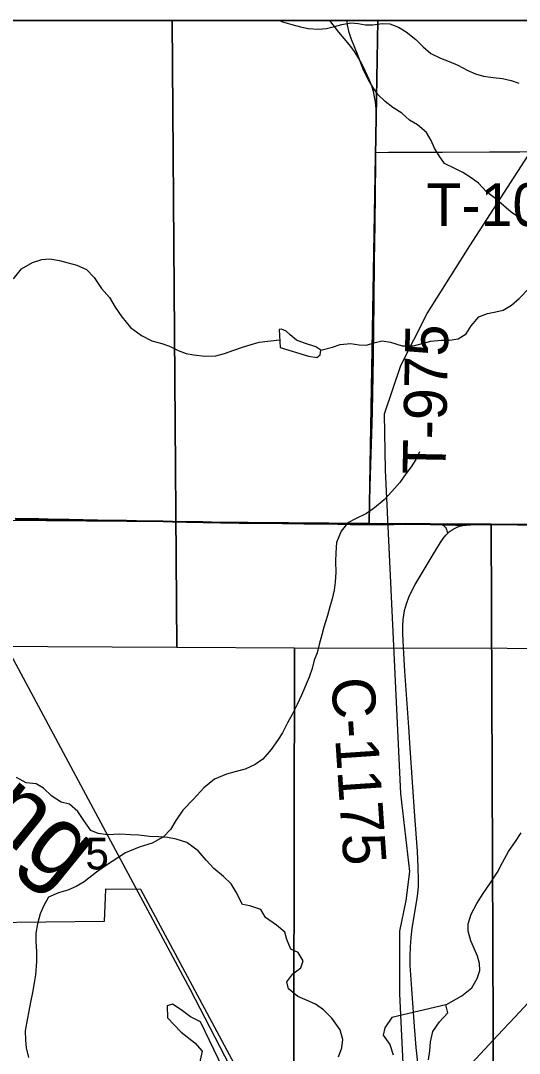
# Model space of a CAD drawing. Extents: x 0 to 34, y 0 to 22.
# Drawn here: x 14.495 to 15.155, y 19.533 to 20.9 of the extents above; entities that cross this region are included whole.
import ezdxf

# ---------------------------------------------------------------- set-up
doc = ezdxf.new("R2010")
doc.units = 0
for name, color, linetype in [('Default', 7, 'Continuous'), ('GM_X_Corporation', 7, 'Continuous'), ('GM_X_County_Road', 7, 'Continuous'), ('GM_X_County_Road_Text', 7, 'Continuous'), ('GM_X_Minor_Lake', 7, 'Continuous'), ('GM_X_Minor_River', 7, 'Continuous'), ('GM_X_Minor_River_Text', 7, 'Continuous'), ('GM_X_Rail_Line', 7, 'Continuous'), ('GM_X_Section', 7, 'Continuous'), ('GM_X_Section_Text', 7, 'Continuous'), ('GM_X_State_Route', 7, 'Continuous'), ('GM_X_Township_Road', 7, 'Continuous'), ('GM_X_Township_Road_Text', 7, 'Continuous'), ('GM_X_US_Shield', 7, 'Continuous'), ('SH_Data', 7, 'Continuous')]:
    doc.layers.add(name, color=color, linetype=linetype)

msp = doc.modelspace()

# ---------------------------------------------------------------- linework, layer by layer
at = {"layer": 'Default'}
for points in [[(14.696, 20.9), (13.7002, 20.9), (13.6857, 20.0757), (13.8471, 20.0749), (14.7021, 20.0706)], [(15.6954, 20.9), (14.696, 20.9), (14.7021, 20.0706), (14.8579, 20.0698), (15.7016, 20.0685)]]:
    msp.add_lwpolyline(points, close=True, dxfattribs=at)
at = {"layer": 'GM_X_Corporation'}
msp.add_lwpolyline([(14.8562, 19.3732), (14.6545, 19.7499), (14.6076, 19.7504), (14.6057, 19.7077), (14.451, 19.7058), (14.4529, 19.6807), (14.1925, 19.6806), (14.194, 19.4591)], dxfattribs=at)
at = {"layer": 'GM_X_County_Road'}
for points in [[(15.0807, 20.2318), (15.0847, 20.2323), (15.0908, 20.2328), (15.1063, 20.233), (15.1529, 20.2325), (15.1871, 20.2321), (15.2181, 20.2318), (15.2386, 20.2315), (15.2557, 20.2318)], [(15.0205, 19.7415), (15.0209, 19.7446), (15.0216, 19.7539), (15.0219, 19.7633), (15.0215, 19.7788), (15.0204, 19.8006), (15.0169, 19.847), (15.0109, 19.9368), (15.009, 19.9647), (15.0038, 20.039), (15.002, 20.07), (15.0011, 20.0886), (15.001, 20.0979), (15.0015, 20.1071), (15.0023, 20.1132), (15.0035, 20.1192), (15.0059, 20.1281), (15.0091, 20.1368), (15.0128, 20.1453), (15.0172, 20.1534), (15.0411, 20.1934), (15.0508, 20.2093), (15.0543, 20.2143), (15.0581, 20.2191), (15.0605, 20.2215)], [(15.0605, 20.2215), (15.0626, 20.2232), (15.065, 20.225), (15.0675, 20.2267), (15.0702, 20.2281), (15.073, 20.2294), (15.0762, 20.2307), (15.0807, 20.2318)], [(15.0338, 19.4539), (15.0319, 19.4586), (15.03, 19.4647), (15.0281, 19.4714), (15.0263, 19.4802), (15.0242, 19.4941), (15.0216, 19.513), (15.0186, 19.5408), (15.0166, 19.5686), (15.0131, 19.6183), (15.0109, 19.6492), (15.0108, 19.6615), (15.0112, 19.6739), (15.0121, 19.6863), (15.0136, 19.6985), (15.0198, 19.7353), (15.0205, 19.7415)]]:
    msp.add_lwpolyline(points, dxfattribs=at)
at = {"layer": 'GM_X_Minor_Lake'}
for points in [[(14.8386, 20.4674), (14.8763, 20.4559), (14.8873, 20.4541), (14.8919, 20.4576), (14.8926, 20.4636), (14.8861, 20.4682), (14.8708, 20.473), (14.8602, 20.4771), (14.8521, 20.4843), (14.8468, 20.4888), (14.8407, 20.4914), (14.8373, 20.491)], [(14.8373, 20.491), (14.8386, 20.4674)], [(14.7752, 19.4876), (14.7335, 19.5749), (14.7203, 19.5814), (14.7078, 19.5906), (14.6964, 19.5979), (14.6892, 19.5957), (14.6895, 19.5801), (14.7076, 19.561), (14.7258, 19.5468), (14.7356, 19.5357), (14.7321, 19.5201)], [(15.0581, 19.5973), (14.9865, 19.5804)], [(15.0352, 19.5242), (15.0366, 19.5363), (15.0377, 19.5481), (15.0406, 19.5618), (15.0496, 19.5748), (15.0605, 19.5867), (15.0581, 19.5973)], [(14.9865, 19.5804), (14.9771, 19.5667), (14.9749, 19.5572), (14.9837, 19.5447), (14.9884, 19.531)]]:
    msp.add_lwpolyline(points, dxfattribs=at)
at = {"layer": 'GM_X_Minor_River'}
for points in [[(14.838, 20.9), (14.8419, 20.8986), (14.8541, 20.8948), (14.8655, 20.8919), (14.8758, 20.8897), (14.8894, 20.8886), (14.9001, 20.8895), (14.9107, 20.8922), (14.9205, 20.895), (14.9323, 20.8973), (14.9418, 20.8963), (14.9517, 20.8944), (14.9616, 20.8945), (14.9737, 20.8961), (14.984, 20.8958), (14.9954, 20.8913), (15.0053, 20.8853), (15.0183, 20.8752), (15.0279, 20.8653), (15.0382, 20.8567), (15.0508, 20.8503), (15.0623, 20.8458), (15.0737, 20.841), (15.0871, 20.8342), (15.0974, 20.8297), (15.108, 20.8264), (15.1206, 20.8246), (15.1331, 20.8235), (15.1445, 20.8206), (15.1548, 20.8172)], [(15.1663, 20.6318), (15.1542, 20.6398), (15.1444, 20.6467), (15.1346, 20.6548), (15.124, 20.6643), (15.1119, 20.6732), (15.1014, 20.685), (15.0915, 20.6919), (15.0806, 20.6992), (15.0707, 20.7038), (15.0563, 20.7111), (15.0492, 20.7211), (15.0432, 20.7314), (15.0387, 20.7413), (15.0323, 20.752), (15.0206, 20.7623), (15.01, 20.7681), (14.9998, 20.7776), (14.988, 20.7849), (14.9778, 20.793), (14.968, 20.8022), (14.9612, 20.8121), (14.9556, 20.8216), (14.9496, 20.8335), (14.9455, 20.8437), (14.9421, 20.8536), (14.9372, 20.8655), (14.9331, 20.875), (14.9301, 20.8845), (14.9279, 20.894), (14.9272, 20.9)], [(14.486, 20.5583), (14.4966, 20.5713), (14.5109, 20.5798), (14.5234, 20.5837), (14.5341, 20.5845), (14.5466, 20.5824), (14.5565, 20.5798), (14.5695, 20.5764), (14.5824, 20.5705), (14.5928, 20.5599), (14.6024, 20.5455), (14.6128, 20.5334), (14.6205, 20.5206), (14.6293, 20.5081), (14.6408, 20.4937), (14.6553, 20.4832), (14.6691, 20.4761), (14.682, 20.4727), (14.6923, 20.469), (14.7038, 20.4634), (14.7144, 20.4593), (14.7243, 20.4575), (14.7392, 20.4557), (14.7536, 20.4562), (14.765, 20.4593), (14.7775, 20.4639), (14.7888, 20.4678), (14.7991, 20.4709), (14.8108, 20.4744), (14.838, 20.4774)], [(14.8926, 20.4636), (14.9081, 20.4679), (14.918, 20.4714), (14.932, 20.4727), (14.9434, 20.4709), (14.9529, 20.4706), (14.9628, 20.4737), (14.9738, 20.476), (14.9848, 20.4742), (15.0004, 20.4694), (15.0152, 20.4695), (15.038, 20.4757), (15.0516, 20.477), (15.0627, 20.4771), (15.0744, 20.4787), (15.085, 20.4856), (15.0914, 20.4959), (15.1015, 20.5078), (15.1133, 20.5124), (15.1243, 20.5144), (15.1337, 20.5168), (15.1451, 20.5233), (15.1549, 20.5321), (15.1685, 20.5463)], [(15.0232, 20.3293), (15.0184, 20.319), (15.012, 20.3094), (15.0049, 20.2999), (14.997, 20.2888), (14.9864, 20.2769), (14.9763, 20.2658), (14.9638, 20.2551), (14.9529, 20.2478), (14.9385, 20.2404), (14.9283, 20.2354), (14.9196, 20.2243), (14.9133, 20.2091), (14.9123, 20.1954), (14.912, 20.184), (14.9125, 20.1699), (14.9114, 20.1566), (14.9104, 20.1463), (14.9074, 20.1345), (14.9045, 20.1239), (14.9015, 20.1124), (14.8967, 20.0972), (14.8938, 20.0869), (14.8905, 20.074), (14.8875, 20.0633), (14.8838, 20.0534), (14.8809, 20.0423), (14.8772, 20.0309), (14.8671, 20.0069), (14.8611, 19.9947), (14.8548, 19.9813), (14.8484, 19.9706), (14.8417, 19.9573), (14.8353, 19.947), (14.827, 19.9351), (14.8157, 19.9225), (14.8055, 19.9152), (14.7923, 19.909), (14.7805, 19.9062), (14.7677, 19.9027), (14.7518, 19.8958), (14.7378, 19.8843), (14.7242, 19.8693), (14.7099, 19.8548), (14.7005, 19.8414), (14.6934, 19.8292), (14.6844, 19.8196), (14.6693, 19.8111), (14.6522, 19.8061), (14.634, 19.7983), (14.6076, 19.7814), (14.5955, 19.773), (14.5793, 19.7599), (14.5687, 19.7537), (14.5577, 19.7491), (14.5452, 19.7456), (14.5323, 19.7398), (14.526, 19.7287), (14.5211, 19.7177), (14.5174, 19.7043), (14.5156, 19.6921), (14.5153, 19.6811), (14.5162, 19.6678), (14.5163, 19.6545), (14.5149, 19.637), (14.5131, 19.6264), (14.511, 19.6134), (14.5084, 19.6005), (14.5062, 19.5887), (14.504, 19.5773), (14.5015, 19.5628), (14.5016, 19.5506), (14.5028, 19.5404), (14.5056, 19.5275)], [(14.9161, 19.5282), (14.9202, 19.5404), (14.9216, 19.5514), (14.9181, 19.5639), (14.9073, 19.5794), (14.8962, 19.5904), (14.8855, 19.5979), (14.8744, 19.6028), (14.8622, 19.608), (14.8496, 19.6182), (14.8476, 19.6277), (14.8555, 19.6384), (14.8661, 19.646), (14.8694, 19.6556), (14.8625, 19.6665), (14.853, 19.6707), (14.8476, 19.6835), (14.8448, 19.6934), (14.8337, 19.7028), (14.8192, 19.713), (14.813, 19.7236), (14.7986, 19.7284), (14.7887, 19.7299), (14.7805, 19.7465), (14.774, 19.7575), (14.7637, 19.7669), (14.751, 19.7775), (14.7407, 19.7888), (14.7303, 19.8009), (14.7154, 19.8122), (14.7009, 19.8167), (14.6895, 19.8185), (14.6777, 19.8195), (14.666, 19.8202), (14.6519, 19.8216), (14.6412, 19.8223), (14.6264, 19.8229), (14.6109, 19.8221), (14.5979, 19.8239), (14.5884, 19.828), (14.5788, 19.8412), (14.5711, 19.8533), (14.56, 19.8627), (14.5489, 19.8653), (14.5367, 19.8732), (14.5256, 19.8842), (14.5157, 19.8898), (14.5028, 19.8912), (14.4898, 19.8983)], [(15.0581, 19.5973), (15.0793, 19.6093), (15.0922, 19.6196), (15.0996, 19.6322), (15.103, 19.6425), (15.1025, 19.652), (15.0998, 19.6615), (15.0959, 19.671), (15.0909, 19.682), (15.0877, 19.6949), (15.0877, 19.7044), (15.0913, 19.7173), (15.0988, 19.7314), (15.1075, 19.7444), (15.1172, 19.7586), (15.1262, 19.7727), (15.1329, 19.7857), (15.1408, 19.8002), (15.1502, 19.8132), (15.1577, 19.825)]]:
    msp.add_lwpolyline(points, dxfattribs=at)
at = {"layer": 'GM_X_Rail_Line'}
for points in [[(18.977, 20.9), (13.2404, 20.9)], [(14.9734, 19.1277), (14.7202, 19.6169), (14.4, 20.214), (14.1926, 20.8038), (14.1778, 20.847), (14.1617, 20.9)], [(15.0133, 19.1903), (15.0101, 19.1984), (15.0603, 19.3577), (15.0194, 19.4377), (15.0025, 19.501), (14.997, 19.6118), (14.9971, 19.6949), (15.0054, 19.7354), (15.0102, 19.7735), (14.9983, 19.877), (14.9781, 20.305), (14.9767, 20.3796), (14.9986, 20.4433), (15.0332, 20.5125), (15.0896, 20.6017), (15.1896, 20.7564), (15.2848, 20.9)], [(15.1869, 20.2327), (15.1527, 20.233), (15.1061, 20.2336), (15.0906, 20.2334), (15.0845, 20.2329), (15.0805, 20.2323), (15.0704, 20.2327), (15.0637, 20.2329), (15.0588, 20.2331), (15.053, 20.2333), (15.0373, 20.2337), (15.0281, 20.2339), (15.0049, 20.2342), (14.9724, 20.2337), (14.9565, 20.2338), (14.9317, 20.2336), (14.8978, 20.2343), (14.8699, 20.2343), (14.8417, 20.2349), (14.7843, 20.2352), (14.7598, 20.2357), (14.7364, 20.2364), (14.7147, 20.2367), (14.6961, 20.2371), (14.6837, 20.2373), (14.6485, 20.2381), (14.6352, 20.2383), (14.6155, 20.2385), (14.5969, 20.2388), (14.5596, 20.2397), (14.5317, 20.2401), (14.5192, 20.2404), (14.4882, 20.2408)], [(14.4882, 20.2408), (14.5192, 20.2404), (14.5317, 20.2401), (14.5596, 20.2397), (14.5969, 20.2388), (14.6155, 20.2385), (14.6352, 20.2383), (14.6485, 20.2381), (14.6837, 20.2373), (14.6961, 20.2371), (14.7147, 20.2367), (14.7364, 20.2364), (14.7598, 20.2357), (14.7843, 20.2352), (14.8417, 20.2349), (14.8699, 20.2343), (14.8978, 20.2343), (14.9317, 20.2336), (14.9565, 20.2338), (14.9724, 20.2337), (15.0049, 20.2342), (15.0281, 20.2339), (15.0373, 20.2337), (15.053, 20.2333), (15.0588, 20.2331), (15.0637, 20.2329), (15.0704, 20.2327), (15.0805, 20.2323), (15.0845, 20.2329), (15.0906, 20.2334), (15.1061, 20.2336), (15.1527, 20.233), (15.1869, 20.2327)]]:
    msp.add_lwpolyline(points, dxfattribs=at)
at = {"layer": 'GM_X_Section'}
for points in [[(14.9565, 20.2348), (15.1179, 20.234), (15.1219, 19.2324), (14.1009, 19.242), (14.1011, 20.2418)], [(15.973, 20.2298), (16.1287, 20.2289), (16.1266, 19.2189), (15.1219, 19.2324), (15.1179, 20.234)], [(14.7021, 20.0706), (14.8579, 20.0698), (14.8558, 19.0597), (13.8511, 19.0732), (13.8471, 20.0749)], [(15.7016, 20.0685), (15.8607, 20.0692), (15.8625, 19.0546), (14.8558, 19.0597), (14.8579, 20.0698)]]:
    msp.add_lwpolyline(points, close=True, dxfattribs=at)
at = {"layer": 'GM_X_State_Route'}
msp.add_lwpolyline([(15.0338, 19.4539), (15.0655, 19.49), (15.0925, 19.5201), (15.1263, 19.5566), (15.1497, 19.5815), (15.1836, 19.6179), (15.2069, 19.643), (15.2598, 19.6999), (15.283, 19.7249), (15.2981, 19.7412)], dxfattribs=at)
at = {"layer": 'GM_X_Township_Road'}
for points in [[(14.9654, 20.7253), (14.9656, 20.752), (14.9658, 20.7738), (14.9656, 20.7831), (14.9648, 20.7924), (14.9638, 20.7985), (14.9625, 20.8046), (14.9599, 20.8136), (14.9566, 20.8223), (14.9512, 20.8335), (14.9458, 20.8446), (14.9404, 20.8542), (14.9361, 20.8603), (14.9305, 20.8678), (14.9165, 20.8847), (14.9043, 20.9)], [(14.9567, 20.2332), (14.9568, 20.2386), (14.9576, 20.2703), (14.9584, 20.2976), (14.9592, 20.3262), (14.96, 20.3528), (14.9608, 20.3822), (14.9621, 20.4536), (14.9628, 20.4909), (14.9631, 20.5282), (14.9636, 20.5811), (14.9643, 20.6308), (14.9655, 20.7116), (14.9654, 20.7253)], [(14.9654, 20.7253), (14.9822, 20.7257), (15.0085, 20.726), (15.0537, 20.7261), (15.1157, 20.7264), (15.156, 20.7265), (15.1839, 20.7268), (15.2149, 20.727), (15.249, 20.7267), (15.277, 20.7266), (15.3189, 20.7267)], [(14.4884, 20.2403), (14.5195, 20.2398), (14.5319, 20.2396), (14.5598, 20.2391), (14.5971, 20.2383), (14.6157, 20.238), (14.6354, 20.2378), (14.6487, 20.2376), (14.6839, 20.2368), (14.6964, 20.2366), (14.715, 20.2362), (14.7367, 20.2358), (14.76, 20.2351), (14.7845, 20.2346), (14.8419, 20.2343), (14.8701, 20.2338), (14.898, 20.2338), (14.9319, 20.233), (14.9567, 20.2332)], [(14.9567, 20.2332), (14.9724, 20.2328), (15.0052, 20.2334), (15.0284, 20.2333), (15.0375, 20.2331), (15.0532, 20.2327)], [(15.0532, 20.2327), (15.0591, 20.2326), (15.0639, 20.2324), (15.0706, 20.2322), (15.0807, 20.2318)], [(15.0532, 20.2327), (15.0549, 20.2315), (15.056, 20.2307), (15.0568, 20.23), (15.0576, 20.2289), (15.0583, 20.2279), (15.0589, 20.2265), (15.0595, 20.2247), (15.0605, 20.2215)]]:
    msp.add_lwpolyline(points, dxfattribs=at)
at = {"layer": 'GM_X_US_Shield'}
for points in [[(14.9682, 20.9), (13.962, 20.9), (13.9544, 20.243), (14.1011, 20.2418), (14.9565, 20.2348)], [(15.968, 20.9), (14.9682, 20.9), (14.9565, 20.2348), (15.1179, 20.234), (15.973, 20.2298)]]:
    msp.add_lwpolyline(points, close=True, dxfattribs=at)
at = {"layer": 'SH_Data'}
msp.add_line((13.2404, 20.9), (20.0404, 20.9), dxfattribs=at)

# ---------------------------------------------------------------- texts
at = {"layer": 'GM_X_County_Road_Text'}
msp.add_text('C-1175', height=0.05682, rotation=273.8895, dxfattribs=at).set_placement((14.9062, 20.029))
at = {"layer": 'GM_X_Minor_River_Text'}
msp.add_text('Lang', height=0.09473, rotation=320.9519, dxfattribs=at).set_placement((14.3318, 19.9292))
at = {"layer": 'GM_X_Section_Text'}
msp.add_text('5', height=0.0419, rotation=0, dxfattribs=at).set_placement((14.581, 19.7764))
at = {"layer": 'GM_X_Township_Road_Text'}
for s, rotation, p in [('T-1054', 0, (15.0322, 20.628)), ('T-975', 88.8719, (15.0575, 20.2989))]:
    msp.add_text(s, height=0.05682, rotation=rotation, dxfattribs=at).set_placement(p)

doc.saveas('drawing.dxf')
